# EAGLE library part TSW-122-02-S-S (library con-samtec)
THROUGH-HOLE .025" SQ POST HEADER Source: Samtec TSW.pdf
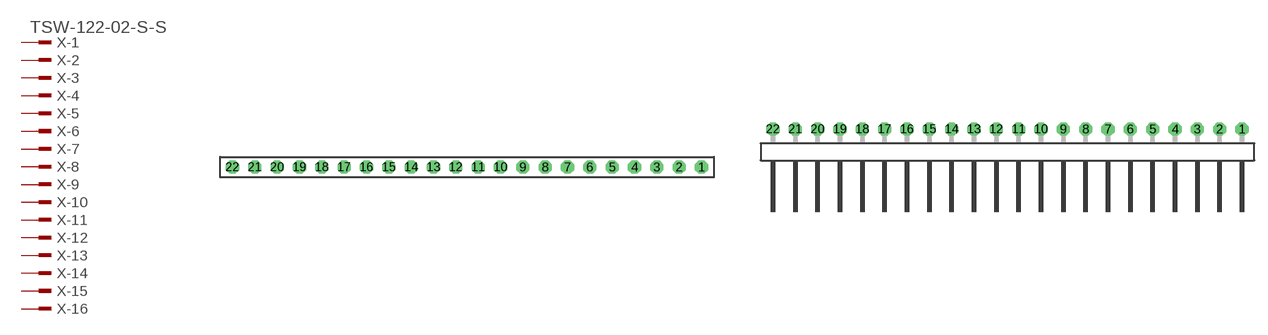
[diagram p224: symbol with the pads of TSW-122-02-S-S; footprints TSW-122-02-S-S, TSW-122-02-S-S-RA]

Designator prefix X; gates -1=MPINV -2=MPIN -3=MPIN -4=MPIN -5=MPIN -6=MPIN -7=MPIN -8=MPIN -9=MPIN -10=MPIN -11=MPIN -12=MPIN -13=MPIN -14=MPIN -15=MPIN -16=MPIN -17=MPIN -18=MPIN -19=MPIN -20=MPIN -21=MPIN -22=MPIN

## TSW-122-02-S-S (OC_FARNELL: unknown; OC_NEWARK: unknown)  [TSW-122-02-S-S]
1  -1:1  pas
2  -2:1  pas
3  -3:1  pas
4  -4:1  pas
5  -5:1  pas
6  -6:1  pas
7  -7:1  pas
8  -8:1  pas
9  -9:1  pas
10  -10:1  pas
11  -11:1  pas
12  -12:1  pas
13  -13:1  pas
14  -14:1  pas
15  -15:1  pas
16  -16:1  pas
17  -17:1  pas
18  -18:1  pas
19  -19:1  pas
20  -20:1  pas
21  -21:1  pas
22  -22:1  pas

## TSW-122-02-S-S-RA (OC_FARNELL: unknown; OC_NEWARK: unknown)  [TSW-122-02-S-S-RA]
Pads as for TSW-122-02-S-S

## Footprint TSW-122-02-S-S (pad centres in mm)
THROUGH-HOLE .025" SQ POST HEADER Source: Samtec TSW.pdf
drill 1 pad 1.5 octagon: 1 26.67,0; 2 24.13,0; 3 21.59,0; 4 19.05,0; 5 16.51,0; 6 13.97,0; 7 11.43,0; 8 8.89,0; 9 6.35,0; 10 3.81,0; 11 1.27,0; 12 -1.27,0; 13 -3.81,0; 14 -6.35,0; 15 -8.89,0; 16 -11.43,0; 17 -13.97,0; 18 -16.51,0; 19 -19.05,0; 20 -21.59,0; 21 -24.13,0; 22 -26.67,0

## Footprint TSW-122-02-S-S-RA (pad centres in mm)
THROUGH-HOLE .025" SQ POST HEADER Source: Samtec TSW.pdf
drill 1 pad 1.5 octagon: 1 26.67,1.524; 2 24.13,1.524; 3 21.59,1.524; 4 19.05,1.524; 5 16.51,1.524; 6 13.97,1.524; 7 11.43,1.524; 8 8.89,1.524; 9 6.35,1.524; 10 3.81,1.524; 11 1.27,1.524; 12 -1.27,1.524; 13 -3.81,1.524; 14 -6.35,1.524; 15 -8.89,1.524; 16 -11.43,1.524; 17 -13.97,1.524; 18 -16.51,1.524; 19 -19.05,1.524; 20 -21.59,1.524; 21 -24.13,1.524; 22 -26.67,1.524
